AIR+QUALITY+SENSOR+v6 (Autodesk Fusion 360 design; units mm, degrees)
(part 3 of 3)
sketch "Sketch46" plane through (0, 27, 0) normal (0, 1, 0) x axis (-1, 0, 0)
  line L1 (13.5, 35.9142) -> (-13.5, 35.9142)
  line L2 (23.2642, 7.15) -> (23.2642, 26.15)
  line L3 (-13.5, -2.6142) -> (13.5, -2.6142)
  line L4 (-23.2642, 26.15) -> (-23.2642, 7.15)
  line L5 (-32.7, 30) -> (-27, 33.2909)
  line L6 (-32.7, 3) -> (-32.7, 30)
  line L7 (-27, -0.2909) -> (-32.7, 3)
  line L8 (-27, -27.5) -> (-27, -0.2909)
  line L9 (15, -39.5) -> (-15, -39.5)
  line L10 (27, 34.5) -> (27, -27.5)
  line L11 (-22, 39.5) -> (22, 39.5)
  line L12 (-27, 33.2909) -> (-27, 34.5)
  line L13 (-31.5, 26.5) -> (-32.7, 26.5)
  line L14 (-31.5, 29.3072) -> (-31.5, 26.5)
  line L15 (-27, 31.9053) -> (-31.5, 29.3072)
  line L16 (-25.8, 31.9053) -> (-27, 31.9053)
  line L17 (-25.8, 33.1142) -> (-25.8, 31.9053)
  line L18 (-23, 33.1142) -> (-25.8, 33.1142)
  line L19 (-20.6142, 38.3) -> (-20.6142, 35.5)
  line L20 (-14.5, 38.3) -> (-20.6142, 38.3)
  line L21 (-14.5, 39.5) -> (-14.5, 38.3)
  line L22 (-22, 39.5) -> (-14.5, 39.5)
  line L23 (-27, 33.2909) -> (-27, 34.5)
  line L24 (-32.7, 30) -> (-27, 33.2909)
  line L25 (-32.7, 26.5) -> (-32.7, 30)
  line L26 (-18.1142, -33.5) -> (-18.1142, -37.8413)
  line L27 (-25.1773, -31.1142) -> (-20.5, -31.1142)
  line L28 (-25.8, 1.0947) -> (-25.8, -27.5)
  line L29 (-27, 1.0947) -> (-25.8, 1.0947)
  line L30 (-31.5, 3.6928) -> (-27, 1.0947)
  line L31 (-31.5, 6.5) -> (-31.5, 3.6928)
  line L32 (-32.7, 6.5) -> (-31.5, 6.5)
  line L33 (-32.7, 3) -> (-32.7, 6.5)
  line L34 (-27, -0.2909) -> (-32.7, 3)
  line L35 (-27, -27.5) -> (-27, -0.2909)
  line L36 (15, -39.5) -> (-15, -39.5)
  line L37 (27, 34.5) -> (27, -27.5)
  line L38 (6.5, 39.5) -> (22, 39.5)
  line L39 (6.5, 38.3) -> (6.5, 39.5)
  line L40 (20.6142, 38.3) -> (6.5, 38.3)
  line L41 (20.6142, 35.5) -> (20.6142, 38.3)
  line L42 (25.8, 33.1142) -> (23, 33.1142)
  line L43 (25.8, -27.5) -> (25.8, 33.1142)
  line L44 (20.5, -31.1142) -> (25.1773, -31.1142)
  line L45 (18.1142, -37.8413) -> (18.1142, -33.5)
  line L46 (-15, -38.3) -> (15, -38.3)
  arc A1 centre (13.5, 26.15) radius 9.7642 clockwise from (13.5, 35.9142) to (23.2642, 26.15)
  arc A2 centre (13.5, 7.15) radius 9.7642 clockwise from (23.2642, 7.15) to (13.5, -2.6142)
  arc A3 centre (-13.5, 7.15) radius 9.7642 clockwise from (-13.5, -2.6142) to (-23.2642, 7.15)
  arc A4 centre (-13.5, 26.15) radius 9.7642 clockwise from (-23.2642, 26.15) to (-13.5, 35.9142)
  arc A5 centre (-15, -27.5) radius 12 clockwise from (-15, -39.5) to (-27, -27.5)
  arc A6 centre (15, -27.5) radius 12 clockwise from (27, -27.5) to (15, -39.5)
  arc A7 centre (22, 34.5) radius 5 clockwise from (22, 39.5) to (27, 34.5)
  arc A8 centre (-22, 34.5) radius 5 clockwise from (-27, 34.5) to (-22, 39.5)
  circle C1 centre (-23, 35.5) radius 0.9
  arc A9 centre (-23, 35.5) radius 2.3858 clockwise from (-20.6142, 35.5) to (-23, 33.1142)
  arc A10 centre (-22, 34.5) radius 5 clockwise from (-27, 34.5) to (-22, 39.5)
  circle C2 centre (-20.5, -33.5) radius 0.9
  circle C3 centre (23, 35.5) radius 0.9
  circle C4 centre (20.5, -33.5) radius 0.9
  arc A11 centre (-20.5, -33.5) radius 2.3858 clockwise from (-20.5, -31.1142) to (-18.1142, -33.5)
  arc A12 centre (-15, -27.5) radius 10.8 clockwise from (-25.1773, -31.1142) to (-25.8, -27.5)
  arc A13 centre (-15, -27.5) radius 12 clockwise from (-15, -39.5) to (-27, -27.5)
  arc A14 centre (15, -27.5) radius 12 clockwise from (27, -27.5) to (15, -39.5)
  arc A15 centre (22, 34.5) radius 5 clockwise from (22, 39.5) to (27, 34.5)
  arc A16 centre (23, 35.5) radius 2.3858 clockwise from (23, 33.1142) to (20.6142, 35.5)
  arc A17 centre (15, -27.5) radius 10.8 clockwise from (25.8, -27.5) to (25.1773, -31.1142)
  arc A18 centre (20.5, -33.5) radius 2.3858 clockwise from (18.1142, -33.5) to (20.5, -31.1142)
  arc A19 centre (15, -27.5) radius 10.8 clockwise from (18.1142, -37.8413) to (15, -38.3)
  arc A20 centre (-15, -27.5) radius 10.8 clockwise from (-15, -38.3) to (-18.1142, -37.8413)
  circle C5 centre (-23, 35.5) radius 1.5
  circle C6 centre (23, 35.5) radius 1.5
  circle C7 centre (20.5, -33.5) radius 1.5
  circle C8 centre (-20.5, -33.5) radius 1.5
  concentric C1 C5
  concentric C3 C6
  concentric C4 C7
  concentric C2 C8
  dimension "d312" diameter C5 = 3
  dimension "d313" diameter C6 = 3
  dimension "d314" diameter C7 = 3
  dimension "d315" diameter C8 = 3
extrude "Extrude3" cut sketch "Sketch46" profile of C1 C2 C3 C4 C5 C6 C7 C8 against normal blind 2
move "Move8"
component_from_bodies "Body->Comp4"
component_from_bodies "Body->Comp5"
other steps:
base_feature "Base Feature1"
base_feature "Base Feature1"
base_feature "Base Feature1"
base_feature "Base Feature1"
base_feature "Base Feature1"
base_feature "Base Feature1"
base_feature "Base Feature1"
create_component "CreateComponent1"
remove_body "RemoveBody2"
remove_body "RemoveBody3"
remove_body "RemoveBody4"
remove_body "RemoveBody5"
remove_body "RemoveBody6"
remove_body "RemoveBody7"
remove_body "RemoveBody8"
remove_body "RemoveBody9"
remove_body "RemoveBody10"
remove_body "RemoveBody11"
remove_body "RemoveBody12"
remove_body "RemoveBody13"
remove_body "RemoveBody14"
remove_body "RemoveBody15"
remove_body "RemoveBody16"
create_component "CreateComponent2"
create_component "CreateComponent1"
create_component "CreateComponent2"
create_component "CreateComponent3"
create_component "CreateComponent4"
create_component "CreateComponent5"
create_component "CreateComponent6"
create_component "CreateComponent7"
create_component "CreateComponent8"
create_component "CreateComponent9"
create_component "CreateComponent10"
create_component "CreateComponent11"
create_component "CreateComponent12"
create_component "CreateComponent13"
create_component "CreateComponent14"
create_component "CreateComponent15"
create_component "CreateComponent16"
create_component "CreateComponent17"
create_component "CreateComponent18"
create_component "CreateComponent19"
create_component "CreateComponent20"
create_component "CreateComponent1"
create_component "CreateComponent2"
create_component "CreateComponent3"
create_component "CreateComponent3"
create_component "CreateComponent4"
create_component "CreateComponent5"
remove_body "RemoveBody19"
create_component "CreateComponent6"
remove_body "RemoveBody20"
create_component "CreateComponent7"
remove_body "RemoveBody21"
remove_body "RemoveBody22"
remove_body "RemoveBody23"
remove_body "RemoveBody24"
remove_body "RemoveBody25"
create_component "CreateComponent8"
remove_body "RemoveBody26"
create_component "CreateComponent9"
remove_body "RemoveBody27"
